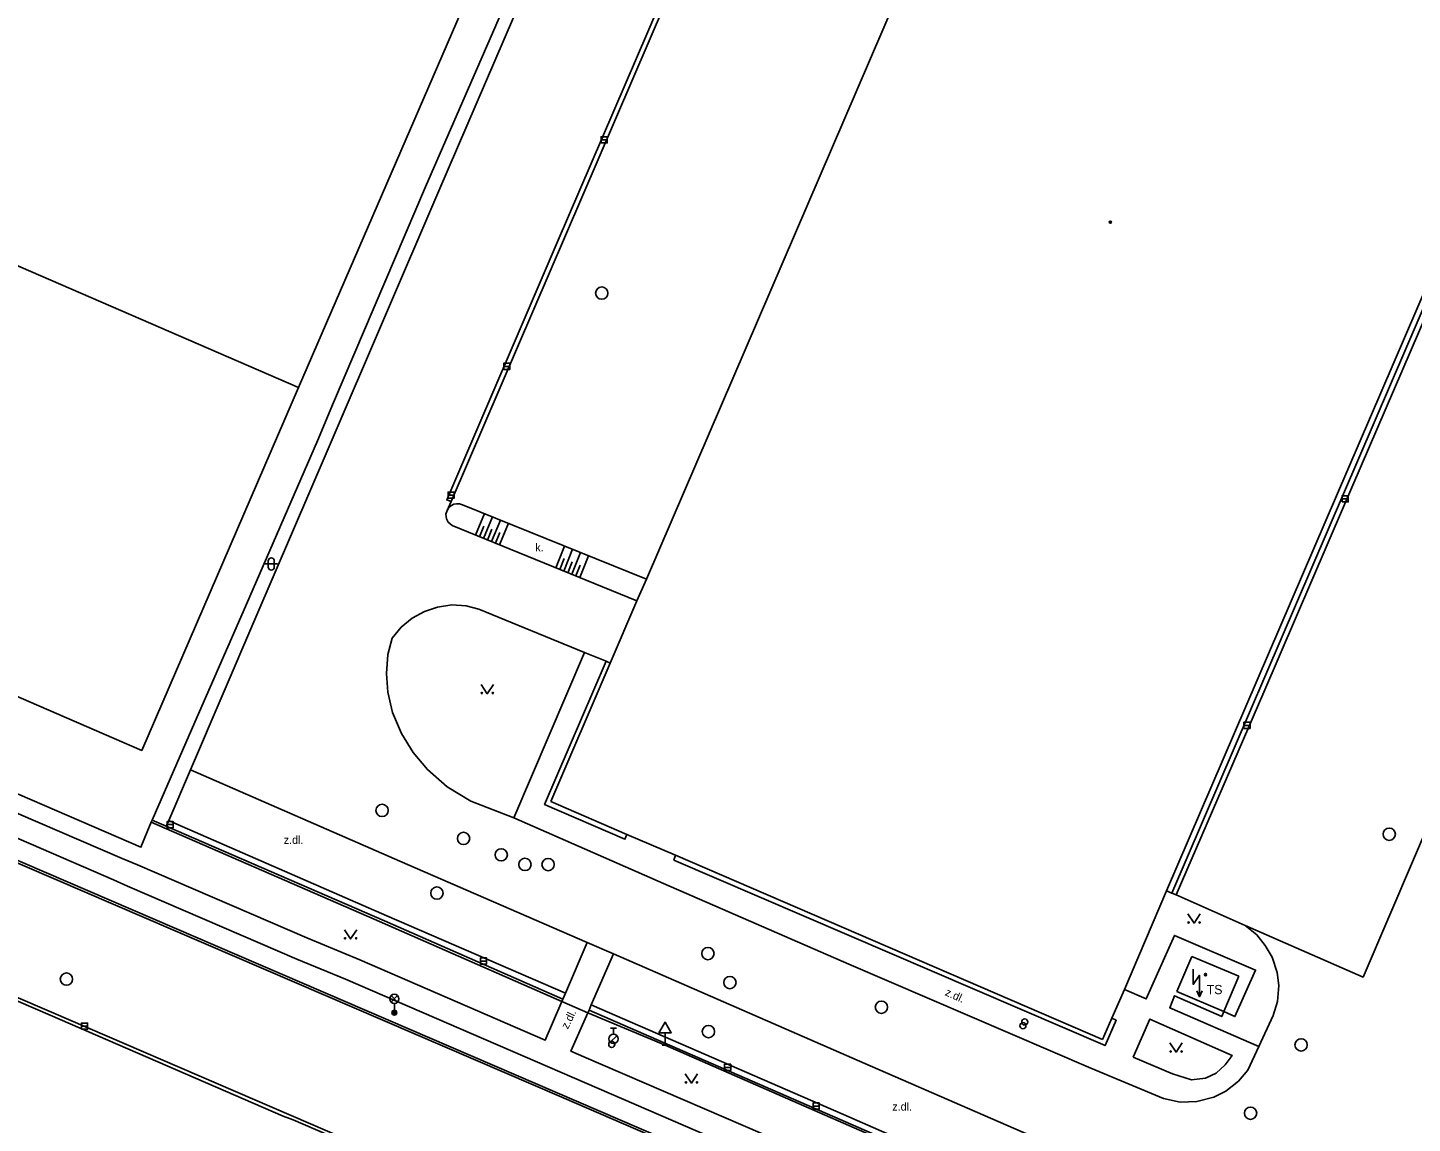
# Model space of a CAD drawing. Extents: x -596024 to -594475, y -1163820 to -1161957.
# Drawn here: x -594681.4 to -594569, y -1162624.8 to -1162535.8 of the extents above; entities that cross this region are included whole.
import ezdxf

# ---------------------------------------------------------------- set-up
doc = ezdxf.new("R2010")
doc.units = 0
for name, color, linetype in [('Level 10', 7, 'Continuous'), ('Level 11', 7, 'Continuous'), ('Level 15', 7, 'Continuous'), ('Level 27', 7, 'Continuous'), ('Level 28', 7, 'Continuous'), ('Level 33', 7, 'Continuous'), ('Level 34', 7, 'Continuous'), ('Level 36', 7, 'Continuous'), ('Level 39', 7, 'Continuous'), ('Level 40', 7, 'Continuous'), ('Level 41', 7, 'Continuous'), ('Level 5', 7, 'Continuous'), ('Level 7', 7, 'Continuous')]:
    doc.layers.add(name, color=color, linetype=linetype)

msp = doc.modelspace()

# ---------------------------------------------------------------- linework, layer by layer
at = {"layer": 'Level 10'}
for points in [[(-594619.35, -1162482.47), (-594624.39, -1162494.17), (-594631.4, -1162510.37), (-594639.67, -1162529.69), (-594648.01, -1162549.08), (-594656.92, -1162569.82), (-594662.95, -1162583.88), (-594668.18, -1162596.08)], [(-594548, -1162678.06), (-594551.53, -1162673.38), (-594555.77, -1162668.36), (-594561.01, -1162662.87), (-594566.52, -1162657.88), (-594571.13, -1162654.23), (-594574.38, -1162651.9), (-594577.98, -1162649.53), (-594580.87, -1162647.82), (-594584.56, -1162645.79), (-594589.75, -1162643.3), (-594617.86, -1162631.14), (-594655.6, -1162614.88), (-594693.79, -1162598.45), (-594730.07, -1162582.86), (-594748.26, -1162574.97), (-594759.55, -1162570.1)], [(-594636.19, -1162586.54), (-594644.77, -1162583.03), (-594645.79, -1162582.77), (-594646.95, -1162582.69), (-594648.11, -1162582.86), (-594649.18, -1162583.22), (-594650.16, -1162583.75), (-594651.06, -1162584.49), (-594651.8, -1162585.38), (-594652.14, -1162586.7), (-594652.26, -1162588.25), (-594652.14, -1162589.76), (-594651.76, -1162591.43), (-594651.05, -1162593.11), (-594650.1, -1162594.67), (-594648.93, -1162596.05), (-594647.34, -1162597.44), (-594645.41, -1162598.62), (-594641.92, -1162599.96)], [(-594634.43, -1162587.24), (-594636.19, -1162586.54)], [(-594634.08, -1162587.41), (-594634.43, -1162587.24)], [(-594668.18, -1162596.08), (-594669.94, -1162600.19)], [(-594637.73, -1162614.2), (-594652.23, -1162607.92), (-594669.27, -1162600.48), (-594669.94, -1162600.19)], [(-594641.92, -1162599.96), (-594629.77, -1162605.3), (-594614.7, -1162611.84), (-594595.06, -1162620.28), (-594589.16, -1162622.75), (-594587.8, -1162623.05), (-594586.45, -1162622.99), (-594585.06, -1162622.64), (-594584.09, -1162622.15), (-594583.06, -1162621.34), (-594582.3, -1162620.45), (-594581.41, -1162618.53)], [(-594588.47, -1162606.09), (-594588.91, -1162605.9)], [(-594588.12, -1162606.22), (-594588.47, -1162606.09)], [(-594582.52, -1162608.7), (-594588.12, -1162606.22)], [(-594581.41, -1162618.53), (-594580.25, -1162616.02), (-594579.9, -1162614.87), (-594579.8, -1162613.57), (-594579.93, -1162612.52), (-594580.34, -1162611.27), (-594580.89, -1162610.32), (-594581.57, -1162609.45), (-594582.52, -1162608.7)], [(-594635.97, -1162610.08), (-594637.73, -1162614.2)], [(-594633.83, -1162611.01), (-594635.97, -1162610.08)], [(-594635.63, -1162615.15), (-594633.83, -1162611.01)], [(-594573.51, -1162642.16), (-594575.44, -1162641.33), (-594582.72, -1162638.13), (-594594.27, -1162633.18), (-594615.14, -1162624.05), (-594634.95, -1162615.44), (-594635.63, -1162615.15)]]:
    msp.add_lwpolyline(points, dxfattribs=at)
at = {"layer": 'Level 11'}
for points in [[(-594609.76, -1162486.67), (-594622.04, -1162515.12), (-594630.12, -1162534.02), (-594638.39, -1162553.28), (-594647.36, -1162574.16), (-594647.01, -1162574.3)], [(-594647.01, -1162574.3), (-594621.63, -1162515.29), (-594611.48, -1162491.7)], [(-594550.4, -1162517.83), (-594560.59, -1162541.26), (-594588.47, -1162606.09)], [(-594588.12, -1162606.22), (-594581.01, -1162589.77), (-594574.54, -1162574.72), (-594567.02, -1162557.26), (-594558.84, -1162538.25), (-594550.03, -1162518)], [(-594550.03, -1162518), (-594534.96, -1162524.57), (-594543.85, -1162545.24), (-594552.11, -1162564.39), (-594559.21, -1162580.96), (-594566.68, -1162598.29), (-594572.95, -1162612.89), (-594582.52, -1162608.7)], [(-594659.39, -1162565.05), (-594672.13, -1162594.49), (-594738.88, -1162565.59)], [(-594760.71, -1162565.78), (-594728.67, -1162579.59), (-594709.93, -1162587.67), (-594692.34, -1162595.26), (-594673.71, -1162603.27), (-594672.49, -1162603.77), (-594658.72, -1162609.72), (-594654.41, -1162611.49), (-594639.36, -1162618.01), (-594638.02, -1162614.88)], [(-594542.36, -1162683.09), (-594546.18, -1162677.82), (-594549.97, -1162672.7), (-594554.75, -1162667.32), (-594558.7, -1162663.05), (-594564.46, -1162657.42), (-594570.53, -1162652.64), (-594573.97, -1162650.2), (-594579, -1162646.99), (-594583.78, -1162644.35), (-594588.95, -1162641.84), (-594601.81, -1162636.27), (-594619.14, -1162628.81), (-594636.99, -1162621.1), (-594655.59, -1162613.05), (-594659.54, -1162611.44), (-594673.3, -1162605.5), (-594674.42, -1162604.99), (-594693.09, -1162596.94), (-594710.64, -1162589.4), (-594729.39, -1162581.33), (-594747.52, -1162573.55), (-594761.45, -1162567.56), (-594763.07, -1162566.87)], [(-594647.34, -1162575.01), (-594647.01, -1162574.3)], [(-594647.34, -1162575.01), (-594647.19, -1162574.78), (-594647.02, -1162574.63), (-594646.8, -1162574.52), (-594646.56, -1162574.48), (-594646.32, -1162574.49), (-594646.09, -1162574.57), (-594631.15, -1162580.59)], [(-594631.92, -1162582.35), (-594646.93, -1162576.25), (-594647.24, -1162575.98), (-594647.39, -1162575.71), (-594647.44, -1162575.31), (-594647.34, -1162575.01)], [(-594636.19, -1162586.54), (-594641.92, -1162599.96)], [(-594632.74, -1162601.31), (-594632.9, -1162601.71), (-594639.42, -1162598.88), (-594634.43, -1162587.24)], [(-594731.51, -1162593.45), (-594712.68, -1162601.48), (-594679.47, -1162615.75), (-594642.1, -1162631.83), (-594623.67, -1162639.79), (-594606.49, -1162647.2), (-594589.45, -1162654.77), (-594588.02, -1162655.56), (-594585.64, -1162656.89), (-594581.84, -1162659.23), (-594579.03, -1162661.16), (-594576.4, -1162663.05), (-594573.78, -1162665.11), (-594571.57, -1162667), (-594567.19, -1162671.07), (-594563.84, -1162674.57), (-594561.52, -1162677.27), (-594559.43, -1162679.87), (-594556.51, -1162684.02), (-594555.42, -1162685.84), (-594554.69, -1162687.42), (-594554.12, -1162689.12), (-594553.77, -1162690.82), (-594553.58, -1162692.52)], [(-594650.56, -1162603.75), (-594668.18, -1162596.08)], [(-594693.86, -1162598.64), (-594637.82, -1162622.71), (-594590.7, -1162643.08), (-594584.59, -1162646.01), (-594577.42, -1162650.16), (-594571.18, -1162654.43), (-594565.76, -1162658.8), (-594561.7, -1162662.7), (-594556.25, -1162668.32), (-594551.36, -1162673.9), (-594538.88, -1162690.77), (-594526.2, -1162708.04)], [(-594670.15, -1162600.65), (-594671.29, -1162600.15)], [(-594637.93, -1162614.68), (-594652.41, -1162608.33), (-594670.15, -1162600.65), (-594669.94, -1162600.19)], [(-594635.97, -1162610.08), (-594650.56, -1162603.75)], [(-594593.34, -1162616.22), (-594593, -1162616.39), (-594593.9, -1162618.45), (-594628.92, -1162603.39), (-594628.79, -1162603.01)], [(-594592.33, -1162613.9), (-594590.56, -1162614.66), (-594588.27, -1162609.51), (-594581.68, -1162612.32), (-594583.36, -1162616.1), (-594584.25, -1162615.69)], [(-594652.02, -1162627.85), (-594659.84, -1162624.49), (-594660.66, -1162624.17), (-594679.57, -1162615.98), (-594689.87, -1162611.56)], [(-594571.69, -1162638.02), (-594583.65, -1162632.85), (-594592.19, -1162629.13), (-594613.41, -1162619.91), (-594633.83, -1162611.01)], [(-594638.02, -1162614.88), (-594637.93, -1162614.68)], [(-594638.02, -1162614.88), (-594635.92, -1162615.8)], [(-594637.93, -1162614.68), (-594637.73, -1162614.2)], [(-594584.25, -1162615.69), (-594584.43, -1162616.1), (-594588.27, -1162614.41), (-594588.65, -1162615.38), (-594581.41, -1162618.53)], [(-594635.92, -1162615.8), (-594637.28, -1162618.91), (-594636.24, -1162619.36), (-594618.39, -1162627.06), (-594600.91, -1162634.59), (-594589.03, -1162639.76), (-594582.92, -1162642.66), (-594577.41, -1162645.7), (-594572.45, -1162648.89), (-594567.89, -1162652.24), (-594563.28, -1162655.94), (-594556.2, -1162662.93), (-594552.13, -1162667.34), (-594548.42, -1162671.61), (-594539, -1162684.2)], [(-594635.81, -1162615.57), (-594635.92, -1162615.8)], [(-594635.63, -1162615.15), (-594635.81, -1162615.57)], [(-594601.58, -1162630.48), (-594615.42, -1162624.44), (-594635.81, -1162615.57)], [(-594591.61, -1162619.38), (-594590.26, -1162616.3), (-594583.59, -1162619.25), (-594584.15, -1162620.01), (-594584.89, -1162620.7), (-594585.76, -1162621.09), (-594586.88, -1162621.24), (-594588.44, -1162620.75), (-594591.61, -1162619.38)]]:
    msp.add_lwpolyline(points, dxfattribs=at)
at = {"layer": 'Level 15'}
for points in [[(-594644.31, -1162575.27), (-594645.02, -1162577.02)], [(-594643.66, -1162575.53), (-594644.37, -1162577.29)], [(-594644.34, -1162576.28), (-594644.7, -1162577.15)], [(-594643.69, -1162576.54), (-594644.05, -1162577.42)], [(-594643.01, -1162575.8), (-594643.72, -1162577.55)], [(-594642.36, -1162576.06), (-594643.07, -1162577.81)], [(-594643.04, -1162576.8), (-594643.4, -1162577.68)], [(-594637.79, -1162577.91), (-594638.5, -1162579.67)], [(-594637.82, -1162578.92), (-594638.18, -1162579.81)], [(-594637.14, -1162578.17), (-594637.85, -1162579.94)], [(-594636.49, -1162578.43), (-594637.21, -1162580.2)], [(-594635.84, -1162578.7), (-594636.56, -1162580.46)], [(-594637.17, -1162579.19), (-594637.53, -1162580.07)], [(-594636.52, -1162579.45), (-594636.88, -1162580.33)]]:
    msp.add_lwpolyline(points, dxfattribs=at)
at = {"layer": 'Level 27'}
for p, q in [((-594634.83, -1162544.94), (-594634.33, -1162544.94)), ((-594642.74, -1162563.32), (-594642.24, -1162563.32)), ((-594647.25, -1162573.77), (-594646.75, -1162573.77)), ((-594574.66, -1162574.07), (-594574.16, -1162574.07)), ((-594582.63, -1162592.46), (-594582.13, -1162592.46)), ((-594670.07, -1162600.52), (-594669.57, -1162600.52)), ((-594644.63, -1162611.59), (-594644.13, -1162611.59)), ((-594677.03, -1162616.88), (-594676.53, -1162616.88)), ((-594624.8, -1162620.22), (-594624.3, -1162620.22)), ((-594617.61, -1162623.36), (-594617.11, -1162623.36))]:
    msp.add_line(p, q, dxfattribs=at)
for points in [[(-594634.83, -1162545.19), (-594634.33, -1162545.19), (-594634.33, -1162544.69), (-594634.83, -1162544.69)], [(-594642.74, -1162563.57), (-594642.24, -1162563.57), (-594642.24, -1162563.07), (-594642.74, -1162563.07)], [(-594647.25, -1162574.02), (-594646.75, -1162574.02), (-594646.75, -1162573.52), (-594647.25, -1162573.52)], [(-594574.66, -1162574.32), (-594574.16, -1162574.32), (-594574.16, -1162573.82), (-594574.66, -1162573.82)], [(-594582.63, -1162592.71), (-594582.13, -1162592.71), (-594582.13, -1162592.21), (-594582.63, -1162592.21)], [(-594670.07, -1162600.77), (-594669.57, -1162600.77), (-594669.57, -1162600.27), (-594670.07, -1162600.27)], [(-594644.63, -1162611.84), (-594644.13, -1162611.84), (-594644.13, -1162611.34), (-594644.63, -1162611.34)], [(-594677.03, -1162617.13), (-594676.53, -1162617.13), (-594676.53, -1162616.63), (-594677.03, -1162616.63)], [(-594624.8, -1162620.47), (-594624.3, -1162620.47), (-594624.3, -1162619.97), (-594624.8, -1162619.97)], [(-594617.61, -1162623.61), (-594617.11, -1162623.61), (-594617.11, -1162623.11), (-594617.61, -1162623.11)]]:
    msp.add_lwpolyline(points, close=True, dxfattribs=at)
for centre in [(-594634.78, -1162557.38), (-594652.62, -1162599.36), (-594646, -1162601.64), (-594570.82, -1162601.3), (-594642.94, -1162602.97), (-594641.01, -1162603.75), (-594639.13, -1162603.76), (-594648.16, -1162606.07), (-594626.15, -1162610.98), (-594678.25, -1162613.06), (-594624.37, -1162613.34), (-594612.07, -1162615.34), (-594626.11, -1162617.32), (-594577.98, -1162618.4), (-594582.09, -1162623.94)]:
    msp.add_circle(centre, 0.5, dxfattribs=at)
at = {"layer": 'Level 28'}
for p, q in [((-594634.07, -1162617.03), (-594633.57, -1162617.03)), ((-594633.82, -1162617.53), (-594633.82, -1162617.03)), ((-594634.08, -1162618.18), (-594633.55, -1162617.65))]:
    msp.add_line(p, q, dxfattribs=at)
for centre, radius in [((-594600.58, -1162616.84), 0.25), ((-594600.42, -1162616.53), 0.25), ((-594633.96, -1162618.36), 0.25), ((-594633.82, -1162617.91), 0.375)]:
    msp.add_circle(centre, radius, dxfattribs=at)
at = {"layer": 'Level 33'}
for p, q in [((-594651.89, -1162614.92), (-594651.36, -1162614.39)), ((-594651.89, -1162614.39), (-594651.36, -1162614.92)), ((-594651.62, -1162615.03), (-594651.62, -1162615.78))]:
    msp.add_line(p, q, dxfattribs=at)
for centre, radius in [((-594651.62, -1162614.66), 0.375), ((-594651.62, -1162615.78), 0.2), ((-594651.62, -1162615.78), 0.145), ((-594651.62, -1162615.78), 0.0876)]:
    msp.add_circle(centre, radius, dxfattribs=at)
at = {"layer": 'Level 34'}
for p, q in [((-594629.63, -1162617.41), (-594629.63, -1162618.43)), ((-594629.88, -1162618.43), (-594629.38, -1162618.43))]:
    msp.add_line(p, q, dxfattribs=at)
msp.add_lwpolyline([(-594630.13, -1162617.41), (-594629.13, -1162617.41), (-594629.63, -1162616.55)], close=True, dxfattribs=at)
at = {"layer": 'Level 36'}
for p, q in [((-594662.12, -1162579.36), (-594661.12, -1162579.36)), ((-594661.87, -1162579.11), (-594661.87, -1162579.61)), ((-594661.37, -1162579.11), (-594661.37, -1162579.61))]:
    msp.add_line(p, q, dxfattribs=at)
for points in [[(-594644.57, -1162589.14), (-594644.07, -1162589.89), (-594643.57, -1162589.14)], [(-594587.17, -1162607.76), (-594586.67, -1162608.51), (-594586.17, -1162607.76)], [(-594655.67, -1162609.05), (-594655.17, -1162609.8), (-594654.67, -1162609.05)], [(-594586.74, -1162612.24), (-594586.74, -1162613.49), (-594586.24, -1162612.74), (-594586.24, -1162614.49)], [(-594586.46, -1162614), (-594586.24, -1162614.49), (-594586.02, -1162614)], [(-594588.63, -1162618.23), (-594588.13, -1162618.98), (-594587.63, -1162618.23)], [(-594627.99, -1162620.74), (-594627.49, -1162621.49), (-594626.99, -1162620.74)]]:
    msp.add_lwpolyline(points, dxfattribs=at)
for centre in [(-594644.52, -1162589.84), (-594643.62, -1162589.84), (-594587.12, -1162608.46), (-594586.22, -1162608.46), (-594655.62, -1162609.75), (-594654.72, -1162609.75), (-594588.58, -1162618.93), (-594587.68, -1162618.93), (-594627.94, -1162621.44), (-594627.04, -1162621.44)]:
    msp.add_circle(centre, 0.05, dxfattribs=at)
for centre, start, end in [((-594661.62, -1162579.11), 0, 180), ((-594661.62, -1162579.61), 180, 0)]:
    msp.add_arc(centre, 0.25, start, end, dxfattribs=at)
at = {"layer": 'Level 39'}
for centre, radius in [((-594593.47, -1162551.62), 0.09), ((-594593.47, -1162551.62), 0.0398), ((-594585.75, -1162612.69), 0.09), ((-594585.75, -1162612.69), 0.0398)]:
    msp.add_circle(centre, radius, dxfattribs=at)
at = {"layer": 'Level 5'}
for points in [[(-594620.92, -1162476.16), (-594659.39, -1162565.05)], [(-594631.15, -1162580.59), (-594595.92, -1162498.74)], [(-594551.11, -1162518.03), (-594588.91, -1162605.9)], [(-594659.39, -1162565.05), (-594726.27, -1162536.09)], [(-594631.92, -1162582.35), (-594631.15, -1162580.59)], [(-594634.08, -1162587.41), (-594631.92, -1162582.35)], [(-594638.92, -1162598.65), (-594634.08, -1162587.41)], [(-594632.74, -1162601.31), (-594638.92, -1162598.65)], [(-594628.79, -1162603.01), (-594632.74, -1162601.31)], [(-594594.1, -1162617.95), (-594628.79, -1162603.01)], [(-594588.91, -1162605.9), (-594592.33, -1162613.9)], [(-594588.08, -1162614.05), (-594586.86, -1162611.21)], [(-594586.86, -1162611.21), (-594583.04, -1162612.82)], [(-594583.04, -1162612.82), (-594584.25, -1162615.69)], [(-594592.33, -1162613.9), (-594593.34, -1162616.22)], [(-594584.25, -1162615.69), (-594588.08, -1162614.05)], [(-594593.34, -1162616.22), (-594594.1, -1162617.95)]]:
    msp.add_lwpolyline(points, dxfattribs=at)
at = {"layer": 'Level 7'}
for points in [[(-594671.37, -1162600.33), (-594671.29, -1162600.15), (-594667.82, -1162592.2), (-594663.9, -1162583.24), (-594657.86, -1162569.37), (-594656.57, -1162566.26), (-594649.08, -1162548.74), (-594640.61, -1162529.29), (-594632.26, -1162509.97), (-594625.26, -1162493.79), (-594620.39, -1162482.75), (-594616.66, -1162474.3)], [(-594761.05, -1162547.48), (-594755.51, -1162566.17), (-594731.46, -1162576.66), (-594688.08, -1162595.5), (-594672.2, -1162602.36), (-594671.37, -1162600.33)], [(-594671.37, -1162600.33), (-594653.25, -1162608.2), (-594638.02, -1162614.88)], [(-594635.92, -1162615.8), (-594629.63, -1162618.43), (-594602.14, -1162630.44), (-594602.48, -1162631.03), (-594600.76, -1162631.82), (-594600.41, -1162631.22), (-594581.9, -1162639.29), (-594567.2, -1162645.66), (-594556.07, -1162650.48), (-594556.01, -1162650.36), (-594553.81, -1162645.71)]]:
    msp.add_lwpolyline(points, dxfattribs=at)

# ---------------------------------------------------------------- texts
at = {"layer": 'Level 40'}
for s, p in [('k. ', (-594640.17, -1162578.34)), ('z.dl.', (-594660.6, -1162602.08)), ('z.dl.', (-594611.18, -1162623.73))]:
    msp.add_text(s, height=0.65, dxfattribs=at).set_placement(p)
for rotation, p in [(336, (-594606.95, -1162614.35)), (63.74, (-594637.53, -1162617.16))]:
    msp.add_text('z.dl.', height=0.65, rotation=rotation, dxfattribs=at).set_placement(p)
at = {"layer": 'Level 41'}
msp.add_text('TS', height=0.75, dxfattribs=at).set_placement((-594585.65, -1162614.28))

doc.saveas('drawing.dxf')
